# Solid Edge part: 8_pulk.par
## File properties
Author: Romil
Template: iso part.par
Last saved by: Romil
Revision: 34
Application: Solid Edge
Accuracy: 0.990
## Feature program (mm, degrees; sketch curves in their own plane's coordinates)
sketch for "unnamed Protrusion 1" plane through (0, 0, 0) normal (1, 0, 0) x-axis (0, 1, 0)
  arc centre (0, 0) radius 2.35 from (2.181, 0.875) to (2.181, -0.875) cw
  arc centre (0, 0) radius 2.35 from (-0.875, 2.181) to (0.875, 2.181) cw
  arc centre (0, 0) radius 2.35 from (-2.181, -0.875) to (-2.181, 0.875) cw
extrude "unnamed Protrusion 1" add finite 63.2 symmetric
fillet "Round_4" radius 0.55  Radii2 = 0.2 mm
mirror "unnamed Mirror 1" of "Round_4" about plane through (0, 0, 0) normal (1, 0, 0)
fillet "unnamed Round 1"
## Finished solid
Body 1: solid body, 50 faces, 128 edges, 80 vertices.
  Faces by surface: cylinder 24, torus 16, plane 10
  Edges by curve: circle 48, line 48, intersection 32
Bounding box of the edges (mm; curved faces can reach further): 63.200 x 4.700 x 4.700, from (-31.6, -2.35, -2.35) to (31.6, 2.35, 2.35).
Cylindrical faces by radius (mm): R0.1 x4, R0.2 x16, R2.35 x4
Toroidal faces (ring radius, tube radius in mm): R0.3 r0.2 x8, R1.8 r0.55 x8
Planar faces by outward normal: +x 1, +y 2, +z 2, -x 1, -y 2, -z 2
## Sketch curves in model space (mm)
arc centre (0, -0.975, -0.975) radius 0.1 from (0, -0.975, -0.875) through (0, -0.9023, -0.9064) to (0, -0.875, -0.975)
line (0, -0.875, -0.975) -> (0, -0.875, -2.181)
arc centre (0, 0, 0) radius 2.35 from (0, 0.875, -2.181) through (0, 0, -2.35) to (0, -0.875, -2.181)
line (0, 0.875, -2.181) -> (0, 0.875, -0.975)
arc centre (0, 0.975, -0.975) radius 0.1 from (0, 0.875, -0.975) through (0, 0.9064, -0.9023) to (0, 0.975, -0.875)
line (0, 0.975, -0.875) -> (0, 2.181, -0.875)
arc centre (0, 0, 0) radius 2.35 from (0, 2.181, 0.875) through (0, 2.35, 0) to (0, 2.181, -0.875)
line (0, 2.181, 0.875) -> (0, 0.975, 0.875)
arc centre (0, 0.975, 0.975) radius 0.1 from (0, 0.975, 0.875) through (0, 0.9023, 0.9064) to (0, 0.875, 0.975)
line (0, 0.875, 0.975) -> (0, 0.875, 2.181)
arc centre (0, 0, 0) radius 2.35 from (0, -0.875, 2.181) through (0, 0, 2.35) to (0, 0.875, 2.181)
line (0, -0.875, 2.181) -> (0, -0.875, 0.975)
arc centre (0, -0.975, 0.975) radius 0.1 from (0, -0.875, 0.975) through (0, -0.9064, 0.9023) to (0, -0.975, 0.875)
line (0, -0.975, 0.875) -> (0, -2.181, 0.875)
arc centre (0, 0, 0) radius 2.35 from (0, -2.181, -0.875) through (0, -2.35, 0) to (0, -2.181, 0.875)
line (0, -2.181, -0.875) -> (0, -0.975, -0.875)
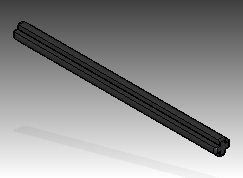
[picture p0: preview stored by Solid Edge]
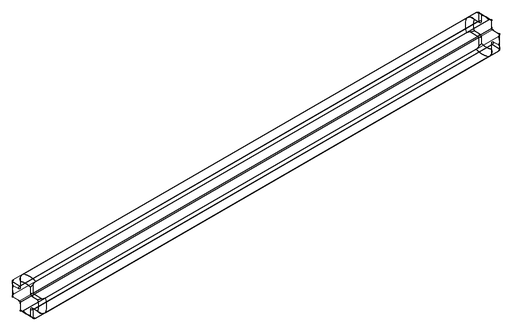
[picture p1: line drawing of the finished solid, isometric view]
